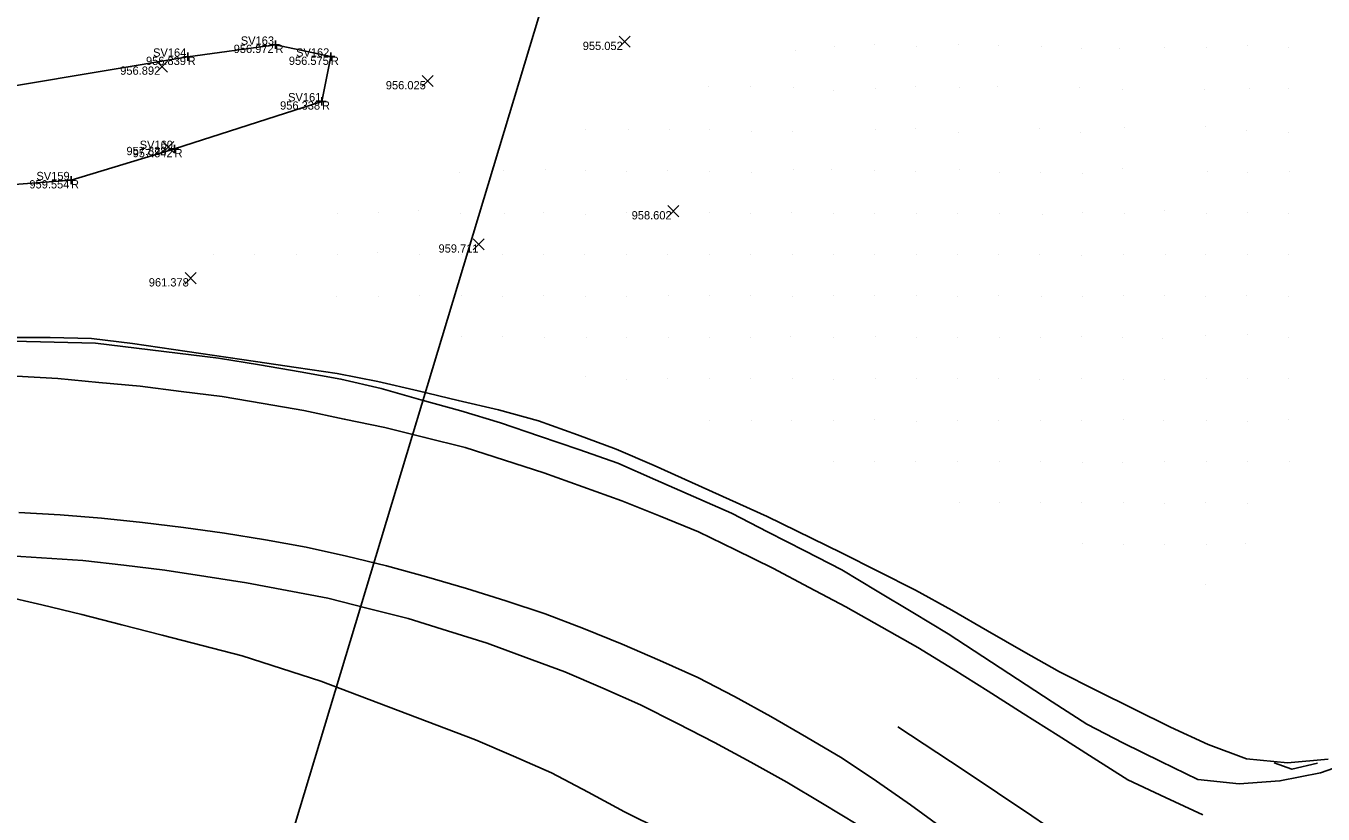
# Model space of a CAD drawing. Extents: x 2262025 to 2264532, y 740981 to 742724.
# Drawn here: x 2262920.9 to 2263077.7, y 741794.3 to 741889.5 of the extents above; entities that cross this region are included whole.
import ezdxf

# ---------------------------------------------------------------- set-up
doc = ezdxf.new("R2010")
doc.units = 0
for name, color, linetype in [('DT_X_Break_Line', 7, 'Continuous'), ('GE_X_Alignment_100_Curve_Data', 7, 'Continuous'), ('GE_X_Alignment_500_Cardinal_Points', 7, 'Continuous'), ('GE_X_Alignment_500_Stations', 7, 'Continuous'), ('Ground Shots', 7, 'Continuous'), ('HY_X_Spring_Cells', 7, 'Continuous'), ('RW_X_CL', 7, 'Continuous'), ('RW_X_CL_1000_Distances', 7, 'Continuous'), ('RW_X_CL_100_Cardinal_Points', 7, 'Continuous'), ('RW_X_CL_500_Stations', 7, 'Continuous'), ('SV_X_Control_Cells_Found', 7, 'Continuous'), ('SV_X_Text_Comment', 7, 'Continuous')]:
    doc.layers.add(name, color=color, linetype=linetype)

msp = doc.modelspace()

# ---------------------------------------------------------------- linework, layer by layer
at = {"layer": 'DT_X_Break_Line'}
msp.add_lwpolyline([(2263092.31, 741760.6), (2263084, 741766.16), (2263075.69, 741771.72), (2263067.37, 741777.28), (2263059.06, 741782.84), (2263050.77, 741788.43), (2263042.51, 741794.07), (2263034.2, 741799.62), (2263026.31, 741804.81)], dxfattribs=at)
at = {"layer": 'GE_X_Alignment_100_Curve_Data'}
for points in [[(2262919.34, 741851.42), (2262924.33, 741851.3), (2262929.33, 741851.17), (2262934.3, 741850.56), (2262939.26, 741849.95), (2262944.22, 741849.34), (2262949.16, 741848.54), (2262954.08, 741847.68), (2262959, 741846.82), (2262963.87, 741845.67), (2262968.68, 741844.33), (2262973.5, 741842.98), (2262978.28, 741841.53), (2262983.02, 741839.93), (2262987.75, 741838.32), (2262992.46, 741836.66), (2262997.04, 741834.65), (2263001.62, 741832.65), (2263006.19, 741830.61), (2263010.64, 741828.33), (2263015.09, 741826.06), (2263019.55, 741823.78), (2263023.83, 741821.2), (2263028.11, 741818.62), (2263032.39, 741816.04), (2263036.59, 741813.32), (2263040.77, 741810.58), (2263044.96, 741807.85), (2263049.16, 741805.14), (2263053.59, 741802.83), (2263058.09, 741800.65), (2263062.59, 741798.48), (2263067.55, 741797.94), (2263072.5, 741798.29), (2263077.39, 741799.28), (2263082.11, 741800.93)], [(2262917.82, 741825.57), (2262922.81, 741825.25), (2262927.8, 741824.93), (2262932.76, 741824.33), (2262937.73, 741823.73), (2262942.67, 741822.97), (2262947.61, 741822.21), (2262952.52, 741821.28), (2262957.43, 741820.35), (2262962.28, 741819.12), (2262967.12, 741817.89), (2262971.9, 741816.41), (2262976.67, 741814.93), (2262981.36, 741813.2), (2262986.05, 741811.46), (2262990.64, 741809.48), (2262995.23, 741807.5), (2262999.69, 741805.23), (2263004.14, 741802.95), (2263008.53, 741800.55), (2263012.91, 741798.15), (2263017.19, 741795.56), (2263021.47, 741792.98)]]:
    msp.add_lwpolyline(points, dxfattribs=at)
at = {"layer": 'GE_X_Alignment_500_Cardinal_Points'}
for p, q in [((2262992.62, 741886.9), (2262993.95, 741888.24)), ((2262992.62, 741888.24), (2262993.95, 741886.9)), ((2262936.72, 741883.91), (2262938.06, 741885.24)), ((2262936.72, 741885.24), (2262938.06, 741883.91)), ((2262968.84, 741882.15), (2262970.17, 741883.49)), ((2262968.84, 741883.49), (2262970.17, 741882.15)), ((2262937.47, 741874.2), (2262938.8, 741875.53)), ((2262937.47, 741875.53), (2262938.8, 741874.2)), ((2262998.53, 741866.44), (2262999.86, 741867.78)), ((2262998.53, 741867.78), (2262999.86, 741866.44)), ((2262974.97, 741862.44), (2262976.3, 741863.77)), ((2262974.97, 741863.77), (2262976.3, 741862.44)), ((2262940.17, 741858.34), (2262941.51, 741859.68)), ((2262940.17, 741859.68), (2262941.51, 741858.34))]:
    msp.add_line(p, q, dxfattribs=at)
at = {"layer": 'GE_X_Alignment_500_Stations'}
msp.add_lwpolyline([(2262899.6, 741869.68), (2262912.08, 741869.76), (2262926.38, 741870.85), (2262938.89, 741874.62), (2262956.71, 741880.37), (2262957.78, 741885.77), (2262951.09, 741887.21), (2262940.48, 741885.76), (2262919.55, 741882.23), (2262906.81, 741881.28), (2262900.64, 741878.45)], close=True, dxfattribs=at)
at = {"layer": 'Ground Shots'}
for p, q in [((2263018.69, 741887.01), (2263018.69, 741887.01)), ((2263023.45, 741887.19), (2263023.45, 741887.19)), ((2263028.53, 741887.05), (2263028.53, 741887.05)), ((2263033.62, 741887.23), (2263033.62, 741887.23)), ((2263038.45, 741887.15), (2263038.45, 741887.15)), ((2263043.66, 741886.95), (2263043.66, 741886.95)), ((2263068.54, 741887.06), (2263068.54, 741887.06)), ((2263013.9, 741886.46), (2263013.9, 741886.46)), ((2263048.53, 741886.81), (2263048.53, 741886.81)), ((2263053.15, 741886.72), (2263053.15, 741886.72)), ((2263058.55, 741886.91), (2263058.55, 741886.91)), ((2263063.66, 741886.86), (2263063.66, 741886.86)), ((2263073.5, 741886.84), (2263073.5, 741886.84)), ((2263003.43, 741882.16), (2263003.43, 741882.16)), ((2263008.51, 741882.15), (2263008.51, 741882.15)), ((2263013.7, 741882.03), (2263013.7, 741882.03)), ((2263018.58, 741881.71), (2263018.58, 741881.71)), ((2263023.59, 741881.87), (2263023.59, 741881.87)), ((2263028.41, 741882.15), (2263028.41, 741882.15)), ((2263033.74, 741882), (2263033.74, 741882)), ((2263038.31, 741882.14), (2263038.31, 741882.14)), ((2263048.22, 741882.05), (2263048.22, 741882.05)), ((2263053.5, 741881.82), (2263053.5, 741881.82)), ((2263063.33, 741881.83), (2263063.33, 741881.83)), ((2263068.77, 741881.94), (2263068.77, 741881.94)), ((2263073.51, 741881.91), (2263073.51, 741881.91)), ((2262988.53, 741876.96), (2262988.53, 741876.96)), ((2262993.7, 741877.02), (2262993.7, 741877.02)), ((2262998.67, 741876.96), (2262998.67, 741876.96)), ((2263003.59, 741876.93), (2263003.59, 741876.93)), ((2263008.64, 741876.68), (2263008.64, 741876.68)), ((2263013.57, 741876.73), (2263013.57, 741876.73)), ((2263023.58, 741876.98), (2263023.58, 741876.98)), ((2263028.49, 741877.04), (2263028.49, 741877.04)), ((2263033.69, 741876.66), (2263033.69, 741876.66)), ((2263043.48, 741877.14), (2263043.48, 741877.14)), ((2263048.43, 741876.62), (2263048.43, 741876.62)), ((2263053.72, 741877.17), (2263053.72, 741877.17)), ((2263063.53, 741877.28), (2263063.53, 741877.28)), ((2263068.47, 741876.79), (2263068.47, 741876.79)), ((2263073.54, 741876.64), (2263073.54, 741876.64)), ((2262973.36, 741871.72), (2262973.36, 741871.72)), ((2262978.61, 741871.97), (2262978.61, 741871.97)), ((2262983.72, 741872.13), (2262983.72, 741872.13)), ((2262988.59, 741872.07), (2262988.59, 741872.07)), ((2262993.55, 741871.89), (2262993.55, 741871.89)), ((2262998.43, 741872), (2262998.43, 741872)), ((2263003.59, 741871.94), (2263003.59, 741871.94)), ((2263008.61, 741871.72), (2263008.61, 741871.72)), ((2263013.71, 741872.13), (2263013.71, 741872.13)), ((2263018.28, 741872.16), (2263018.28, 741872.16)), ((2263023.54, 741871.97), (2263023.54, 741871.97)), ((2263028.4, 741871.95), (2263028.4, 741871.95)), ((2263033.71, 741872.11), (2263033.71, 741872.11)), ((2263038.62, 741871.81), (2263038.62, 741871.81)), ((2263043.55, 741871.83), (2263043.55, 741871.83)), ((2263048.59, 741871.66), (2263048.59, 741871.66)), ((2263053.51, 741872.24), (2263053.51, 741872.24)), ((2263063.7, 741871.94), (2263063.7, 741871.94)), ((2263068.52, 741871.79), (2263068.52, 741871.79)), ((2263073.6, 741871.84), (2263073.6, 741871.84)), ((2262958.55, 741866.85), (2262958.55, 741866.85)), ((2262963.59, 741866.92), (2262963.59, 741866.92)), ((2262968.32, 741867.15), (2262968.32, 741867.15)), ((2262973.44, 741866.83), (2262973.44, 741866.83)), ((2262978.75, 741866.8), (2262978.75, 741866.8)), ((2262983.46, 741866.96), (2262983.46, 741866.96)), ((2262988.59, 741866.74), (2262988.59, 741866.74)), ((2262993.47, 741866.96), (2262993.47, 741866.96)), ((2262998.53, 741866.86), (2262998.53, 741866.86)), ((2263003.55, 741866.91), (2263003.55, 741866.91)), ((2263008.53, 741866.87), (2263008.53, 741866.87)), ((2263013.5, 741866.9), (2263013.5, 741866.9)), ((2263018.55, 741866.83), (2263018.55, 741866.83)), ((2263023.55, 741866.87), (2263023.55, 741866.87)), ((2263028.57, 741866.85), (2263028.57, 741866.85)), ((2263033.55, 741866.88), (2263033.55, 741866.88)), ((2263038.57, 741866.88), (2263038.57, 741866.88)), ((2263043.83, 741866.72), (2263043.83, 741866.72)), ((2263048.6, 741866.97), (2263048.6, 741866.97)), ((2263053.65, 741866.82), (2263053.65, 741866.82)), ((2263058.59, 741867.13), (2263058.59, 741867.13)), ((2263063.57, 741866.88), (2263063.57, 741866.88)), ((2263068.55, 741866.92), (2263068.55, 741866.92)), ((2263073.56, 741866.87), (2263073.56, 741866.87)), ((2262943.6, 741861.89), (2262943.6, 741861.89)), ((2262948.6, 741861.86), (2262948.6, 741861.86)), ((2262953.6, 741861.91), (2262953.6, 741861.91)), ((2262958.56, 741861.89), (2262958.56, 741861.89)), ((2262963.39, 741862.11), (2262963.39, 741862.11)), ((2262968.46, 741861.86), (2262968.46, 741861.86)), ((2262973.55, 741861.83), (2262973.55, 741861.83)), ((2262978.59, 741861.84), (2262978.59, 741861.84)), ((2262983.51, 741861.84), (2262983.51, 741861.84)), ((2262993.56, 741861.87), (2262993.56, 741861.87)), ((2262998.51, 741861.89), (2262998.51, 741861.89)), ((2263003.52, 741861.84), (2263003.52, 741861.84)), ((2263008.56, 741861.85), (2263008.56, 741861.85)), ((2263013.55, 741861.88), (2263013.55, 741861.88)), ((2263018.57, 741861.91), (2263018.57, 741861.91)), ((2263023.51, 741861.9), (2263023.51, 741861.9)), ((2263033.5, 741861.84), (2263033.5, 741861.84)), ((2263038.45, 741861.9), (2263038.45, 741861.9)), ((2263043.48, 741861.88), (2263043.48, 741861.88)), ((2263053.58, 741861.89), (2263053.58, 741861.89)), ((2263058.63, 741861.85), (2263058.63, 741861.85)), ((2263063.51, 741861.9), (2263063.51, 741861.9)), ((2263068.56, 741861.88), (2263068.56, 741861.88)), ((2263073.57, 741861.88), (2263073.57, 741861.88)), ((2262988.49, 741861.82), (2262988.49, 741861.82)), ((2263028.55, 741861.82), (2263028.55, 741861.82)), ((2263048.47, 741861.77), (2263048.47, 741861.77)), ((2262958.48, 741856.81), (2262958.48, 741856.81)), ((2262963.5, 741856.82), (2262963.5, 741856.82)), ((2262968.53, 741856.88), (2262968.53, 741856.88)), ((2262973.53, 741856.87), (2262973.53, 741856.87)), ((2262978.56, 741856.84), (2262978.56, 741856.84)), ((2262983.54, 741856.87), (2262983.54, 741856.87)), ((2262988.55, 741856.83), (2262988.55, 741856.83)), ((2262993.55, 741856.84), (2262993.55, 741856.84)), ((2262998.55, 741856.9), (2262998.55, 741856.9)), ((2263003.56, 741856.87), (2263003.56, 741856.87)), ((2263008.52, 741856.87), (2263008.52, 741856.87)), ((2263013.54, 741856.84), (2263013.54, 741856.84)), ((2263018.53, 741856.86), (2263018.53, 741856.86)), ((2263023.54, 741856.87), (2263023.54, 741856.87)), ((2263028.52, 741856.92), (2263028.52, 741856.92)), ((2263033.58, 741856.84), (2263033.58, 741856.84)), ((2263038.5, 741856.86), (2263038.5, 741856.86)), ((2263043.68, 741856.79), (2263043.68, 741856.79)), ((2263048.6, 741856.85), (2263048.6, 741856.85)), ((2263053.54, 741856.89), (2263053.54, 741856.89)), ((2263058.6, 741856.88), (2263058.6, 741856.88)), ((2263063.55, 741856.83), (2263063.55, 741856.83)), ((2263068.48, 741856.9), (2263068.48, 741856.9)), ((2263073.49, 741856.85), (2263073.49, 741856.85)), ((2262973.52, 741851.91), (2262973.52, 741851.91)), ((2262978.49, 741851.97), (2262978.49, 741851.97)), ((2262983.56, 741851.86), (2262983.56, 741851.86)), ((2262988.63, 741851.84), (2262988.63, 741851.84)), ((2262993.53, 741851.9), (2262993.53, 741851.9)), ((2262998.57, 741851.88), (2262998.57, 741851.88)), ((2263003.51, 741851.85), (2263003.51, 741851.85)), ((2263008.52, 741851.85), (2263008.52, 741851.85)), ((2263013.33, 741851.93), (2263013.33, 741851.93)), ((2263018.59, 741851.82), (2263018.59, 741851.82)), ((2263023.57, 741852), (2263023.57, 741852)), ((2263028.58, 741851.88), (2263028.58, 741851.88)), ((2263033.52, 741851.79), (2263033.52, 741851.79)), ((2263038.54, 741851.86), (2263038.54, 741851.86)), ((2263043.57, 741851.83), (2263043.57, 741851.83)), ((2263048.48, 741851.96), (2263048.48, 741851.96)), ((2263053.5, 741851.84), (2263053.5, 741851.84)), ((2263058.28, 741851.77), (2263058.28, 741851.77)), ((2263063.55, 741852.09), (2263063.55, 741852.09)), ((2263068.58, 741852.17), (2263068.58, 741852.17)), ((2263073.54, 741851.8), (2263073.54, 741851.8)), ((2262988.6, 741847.09), (2262988.6, 741847.09)), ((2262993.52, 741846.83), (2262993.52, 741846.83)), ((2262998.5, 741846.88), (2262998.5, 741846.88)), ((2263003.49, 741846.9), (2263003.49, 741846.9)), ((2263008.53, 741846.84), (2263008.53, 741846.84)), ((2263013.54, 741846.85), (2263013.54, 741846.85)), ((2263018.57, 741846.81), (2263018.57, 741846.81)), ((2263023.58, 741846.86), (2263023.58, 741846.86)), ((2263028.51, 741846.89), (2263028.51, 741846.89)), ((2263033.5, 741846.88), (2263033.5, 741846.88)), ((2263038.51, 741846.92), (2263038.51, 741846.92)), ((2263043.49, 741846.82), (2263043.49, 741846.82)), ((2263048.51, 741846.87), (2263048.51, 741846.87)), ((2263053.53, 741846.83), (2263053.53, 741846.83)), ((2263058.53, 741846.82), (2263058.53, 741846.82)), ((2263063.56, 741846.84), (2263063.56, 741846.84)), ((2263068.63, 741846.87), (2263068.63, 741846.87)), ((2263073.57, 741846.86), (2263073.57, 741846.86)), ((2263003.53, 741841.86), (2263003.53, 741841.86)), ((2263008.59, 741841.85), (2263008.59, 741841.85)), ((2263013.5, 741841.83), (2263013.5, 741841.83)), ((2263018.53, 741841.85), (2263018.53, 741841.85)), ((2263023.54, 741841.89), (2263023.54, 741841.89)), ((2263028.53, 741841.76), (2263028.53, 741841.76)), ((2263033.55, 741841.85), (2263033.55, 741841.85)), ((2263038.51, 741841.87), (2263038.51, 741841.87)), ((2263043.6, 741841.79), (2263043.6, 741841.79)), ((2263048.54, 741841.83), (2263048.54, 741841.83)), ((2263053.59, 741841.89), (2263053.59, 741841.89)), ((2263058.46, 741841.86), (2263058.46, 741841.86)), ((2263063.6, 741841.78), (2263063.6, 741841.78)), ((2263068.56, 741841.74), (2263068.56, 741841.74)), ((2263073.53, 741841.89), (2263073.53, 741841.89)), ((2263018.51, 741836.89), (2263018.51, 741836.89)), ((2263023.53, 741836.9), (2263023.53, 741836.9)), ((2263028.47, 741836.84), (2263028.47, 741836.84)), ((2263033.54, 741836.87), (2263033.54, 741836.87)), ((2263038.55, 741836.86), (2263038.55, 741836.86)), ((2263043.51, 741836.85), (2263043.51, 741836.85)), ((2263048.59, 741836.8), (2263048.59, 741836.8)), ((2263053.49, 741836.8), (2263053.49, 741836.8)), ((2263058.57, 741836.84), (2263058.57, 741836.84)), ((2263063.58, 741836.87), (2263063.58, 741836.87)), ((2263068.52, 741836.89), (2263068.52, 741836.89)), ((2263073.59, 741836.84), (2263073.59, 741836.84)), ((2263033.75, 741831.91), (2263033.75, 741831.91)), ((2263038.54, 741831.88), (2263038.54, 741831.88)), ((2263043.56, 741831.88), (2263043.56, 741831.88)), ((2263048.52, 741831.86), (2263048.52, 741831.86)), ((2263053.54, 741831.88), (2263053.54, 741831.88)), ((2263058.55, 741831.83), (2263058.55, 741831.83)), ((2263063.51, 741831.86), (2263063.51, 741831.86)), ((2263068.62, 741831.82), (2263068.62, 741831.82)), ((2263048.62, 741826.94), (2263048.62, 741826.94)), ((2263053.59, 741826.86), (2263053.59, 741826.86)), ((2263058.51, 741826.84), (2263058.51, 741826.84)), ((2263063.59, 741826.85), (2263063.59, 741826.85)), ((2263068.29, 741827.01), (2263068.29, 741827.01)), ((2263063.55, 741822.01), (2263063.55, 741822.01))]:
    msp.add_line(p, q, dxfattribs=at)
at = {"layer": 'RW_X_CL_1000_Distances'}
for points in [[(2262919.8, 741847.17), (2262924.79, 741846.91), (2262929.76, 741846.43), (2262934.74, 741845.95), (2262939.7, 741845.34), (2262944.66, 741844.72), (2262949.59, 741843.87), (2262954.51, 741843.01), (2262959.4, 741841.99), (2262964.3, 741840.96), (2262969.15, 741839.77), (2262974.01, 741838.57), (2262978.77, 741837.04), (2262983.52, 741835.49), (2262988.23, 741833.81), (2262992.94, 741832.13), (2262997.58, 741830.27), (2263002.21, 741828.39), (2263006.7, 741826.19), (2263011.19, 741823.98), (2263015.61, 741821.66), (2263020.04, 741819.33), (2263024.39, 741816.87), (2263028.74, 741814.4), (2263032.99, 741811.77), (2263037.24, 741809.14), (2263041.46, 741806.45), (2263045.67, 741803.76), (2263049.9, 741801.09), (2263054.12, 741798.42), (2263058.65, 741796.3), (2263063.19, 741794.19)], [(2263031.88, 741792.46), (2263027.84, 741795.41), (2263023.73, 741798.25), (2263019.57, 741801.03), (2263015.27, 741803.58), (2263010.95, 741806.09), (2263006.56, 741808.49), (2263002.13, 741810.8), (2262997.56, 741812.83), (2262992.98, 741814.82), (2262988.34, 741816.68), (2262983.67, 741818.47), (2262978.92, 741820.03), (2262974.16, 741821.55), (2262969.35, 741822.93), (2262964.53, 741824.25), (2262959.67, 741825.44), (2262954.8, 741826.54), (2262949.87, 741827.39), (2262944.94, 741828.2), (2262939.99, 741828.88), (2262935.03, 741829.51), (2262930.06, 741830.01), (2262925.08, 741830.44), (2262920.09, 741830.71)]]:
    msp.add_lwpolyline(points, dxfattribs=at)
at = {"layer": 'RW_X_CL_100_Cardinal_Points'}
for p, q in [((2262950.59, 741887.21), (2262951.59, 741887.21)), ((2262951.09, 741887.71), (2262951.09, 741886.71)), ((2262951.09, 741887.21), (2262951.09, 741887.21)), ((2262939.98, 741885.76), (2262940.98, 741885.76)), ((2262940.48, 741886.26), (2262940.48, 741885.26)), ((2262940.48, 741885.76), (2262940.48, 741885.76)), ((2262957.28, 741885.77), (2262958.28, 741885.77)), ((2262957.78, 741886.27), (2262957.78, 741885.27)), ((2262957.78, 741885.77), (2262957.78, 741885.77)), ((2262956.71, 741880.87), (2262956.71, 741879.87)), ((2262956.21, 741880.37), (2262957.21, 741880.37)), ((2262956.71, 741880.37), (2262956.71, 741880.37)), ((2262938.39, 741874.62), (2262939.39, 741874.62)), ((2262938.89, 741875.12), (2262938.89, 741874.12)), ((2262938.89, 741874.62), (2262938.89, 741874.62)), ((2262926.38, 741871.35), (2262926.38, 741870.35)), ((2262925.88, 741870.85), (2262926.88, 741870.85)), ((2262926.38, 741870.85), (2262926.38, 741870.85))]:
    msp.add_line(p, q, dxfattribs=at)
at = {"layer": 'RW_X_CL_500_Stations'}
msp.add_line((2262983.68, 741893.13), (2262943.22, 741759.19), dxfattribs=at)
at = {"layer": 'SV_X_Control_Cells_Found'}
for points in [[(2262918.87, 741851.85), (2262923.87, 741851.85), (2262928.86, 741851.72), (2262933.82, 741851.13), (2262943.71, 741849.68), (2262948.66, 741848.96), (2262953.61, 741848.24), (2262958.55, 741847.48), (2262963.46, 741846.55), (2262968.32, 741845.4), (2262973.19, 741844.25), (2262978.05, 741843.09), (2262982.87, 741841.77), (2262987.58, 741840.09), (2262992.26, 741838.34), (2262996.85, 741836.37), (2263001.42, 741834.33), (2263005.98, 741832.29), (2263010.53, 741830.22), (2263019.51, 741825.82), (2263023.99, 741823.6), (2263028.45, 741821.34), (2263032.82, 741818.92), (2263037.15, 741816.41), (2263041.48, 741813.91), (2263045.84, 741811.47), (2263050.31, 741809.22), (2263054.78, 741807), (2263059.27, 741804.79), (2263063.8, 741802.67), (2263068.46, 741800.97), (2263073.42, 741800.48), (2263078.34, 741800.93)], [(2262917.97, 741820.68), (2262922.84, 741819.54), (2262927.7, 741818.39), (2262932.54, 741817.15), (2262937.38, 741815.9), (2262942.23, 741814.66), (2262947.07, 741813.41), (2262951.82, 741811.87), (2262956.58, 741810.33), (2262961.25, 741808.56), (2262965.93, 741806.79), (2262970.6, 741805.02), (2262975.28, 741803.24), (2262979.86, 741801.26), (2262984.45, 741799.27), (2262988.87, 741796.93), (2262993.28, 741794.57), (2262997.76, 741792.35)], [(2263071.81, 741800.48), (2263073.94, 741799.7), (2263077.02, 741800.44)]]:
    msp.add_lwpolyline(points, dxfattribs=at)

# ---------------------------------------------------------------- texts
at = {"layer": 'HY_X_Spring_Cells'}
for s, p in [('956.972', (2262946.04, 741886.21)), ('955.052', (2262988.23, 741886.57)), ('956.839', (2262935.44, 741884.76)), ('956.575', (2262952.71, 741884.77)), ('956.892', (2262932.33, 741883.58)), ('956.025', (2262964.43, 741881.82)), ('956.338', (2262951.65, 741879.37)), ('957.828', (2262933.08, 741873.87)), ('957.842', (2262933.83, 741873.62)), ('959.554', (2262921.35, 741869.85)), ('958.602', (2262994.14, 741866.11)), ('959.711', (2262970.8, 741862.1)), ('961.378', (2262935.78, 741858.01))]:
    msp.add_text(s, height=1, dxfattribs=at).set_placement(p)
at = {"layer": 'RW_X_CL'}
for p in [(2262951.09, 741886.21), (2262940.48, 741884.76), (2262957.78, 741884.77), (2262956.71, 741879.37), (2262938.89, 741873.62), (2262926.38, 741869.85)]:
    msp.add_text('R', height=1, dxfattribs=at).set_placement(p)
at = {"layer": 'SV_X_Text_Comment'}
for s, p in [('SV163', (2262946.9, 741887.21)), ('SV164', (2262936.3, 741885.76)), ('SV162', (2262953.58, 741885.77)), ('SV161', (2262952.62, 741880.37)), ('SV160', (2262934.68, 741874.62)), ('SV159', (2262922.2, 741870.85))]:
    msp.add_text(s, height=1, dxfattribs=at).set_placement(p)

doc.saveas('drawing.dxf')
